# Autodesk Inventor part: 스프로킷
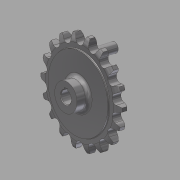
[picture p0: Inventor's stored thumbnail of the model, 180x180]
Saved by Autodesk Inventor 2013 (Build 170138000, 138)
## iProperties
Created: 2016-03
Part Number: 스프로킷
Material: 강철, 탄소
Document SubType Name: Modeling
Designer: mduedu
Density: 7.87 g/cm^3
Mass: 301.857 g
Surface Area: 120.622 cm^2
Volume: 38.3554 cm^3
Author: mduedu
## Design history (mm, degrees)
sketch "스케치1"
  geometry: L1 (0, 5)-(29.5, 5); L2 (29.5, 5)-(29.5, 4.1); L3 (30, 3.6)-(33.625, 3.6); L4 (40, 2)-(40, 0); L5 (40, 0)-(0, 0); L6 (0, 0)-(0, 5); L7 (0, -5)-(29.5, -5); L8 (29.5, -5)-(29.5, -4.1); L9 (30, -3.6)-(33.625, -3.6); L10 (40, -2)-(40, 0); L11 (0, 0)-(0, -5); A1 r 13.5 centre (33.625, -9.9) between (40, 2) and (33.625, 3.6); A2 r 13.5 centre (33.625, 9.9) between (33.625, -3.6) and (40, -2); A3 r 0.5 centre (30, 4.1) between (29.5, 4.1) and (30, 3.6); A4 r 0.5 centre (30, -4.1) between (30, -3.6) and (29.5, -4.1); 2 further points
  constraints: 22 end point, 8 point on circle, 6 symmetric about line, 5 tangent, 4 centre point, 4 parallel, 4 point on line, 1 equal radius, 1 horizontal, 1 perpendicular, 1 other
  dimensions: "d0" = 80 diameter of L4 L6; "d2" = 59 diameter of L2 L6; "d3" = 1.6 vertical distance of L4.start L3.end; "d4" = 3.6 distance from line of L4.end L3; "d5" = 5 distance between parallel lines of L5 L1; "d6" = 13.5 radius of A1; "d15" = 0.5 radius of A3
revolve "회전1" sketch "스케치1" stored, may be unused: angle "d7" = 90 deg
sketch "스케치2" dims "d8" = 65.2, "d11" = 80
  geometry: L1 (0, 0)-(0, 32.6); A1 r 36.57 centre (0, 0) between (-16.231, 32.771) and (0, 36.57); A2 r 3.97 centre (0, 36.57) between (-3.866, 35.665) and (0, 32.6); A3 r 12.7 centre (-16.231, 32.771) between (-3.866, 35.665) and (-5.534, 39.615); A4 r 12.7 centre (16.231, 32.771) between (5.534, 39.615) and (3.866, 35.665); A5 r 3.97 centre (0, 36.57) between (0, 32.6) and (3.866, 35.665); A6 r 40 centre (0, 0) between (5.534, 39.615) and (-5.534, 39.615); 2 further points
  constraints: 12 point on circle, 6 centre point, 4 coincident, 3 symmetric about line, 2 end point, 1 point on line, 1 tangent, 1 vertical, 1 vertical alignment, 7 other
  dimensions: "d10" = 73.14 diameter of A1; "d12" = 12.7 radius of A3
extrude "돌출1" cut sketch "스케치2" stored distance "d13" = 10; taper "d14" = 0 deg
sketch "스케치3"
  geometry: C1 r 11 at (0, 0); 1 further point
  constraints: 1 centre point, 1 coincident
  dimensions: "d19" = 22 diameter of C1
extrude "돌출2" join sketch "스케치3" distance "d20" = 10; taper "d21" = 0 deg
fillet "모깎기1" dims "d22" = 3
sketch "스케치4"
  geometry: L1 (-1.5, 0)-(1.5, 0); L2 (1.5, 0)-(1.5, 6.4); L3 (1.5, 6.4)-(-1.5, 6.4); L4 (-1.5, 6.4)-(-1.5, 0); C1 r 5 at (0, 0); 2 further points
  constraints: 8 end point, 2 coincident, 2 parallel, 1 centre point, 1 horizontal, 1 midpoint, 1 perpendicular
  dimensions: "d23" = 10 diameter of C1; "d25" = 3 distance of L2.end L3.end; "d26" = 6.4 distance of L1.end L2.end
extrude "돌출3" cut sketch "스케치4" stored distance "d27" = 8; taper "d28" = 0 deg
chamfer "모따기1" distance "d29" = 0.5; stored, may be unused: second distance "d30" = 2, angle "d31" = 45 deg
sketch "스케치5" dims "d33" = 48
  geometry: C1 r 4 at (0, 24); 2 further points
  constraints: 2 vertical alignment, 1 centre point, 1 coincident, 2 other
  dimensions: "d32" = 8 diameter of C1
extrude "돌출4" join sketch "스케치5" distance "d34" = 20; taper "d35" = 0 deg
fillet "모깎기2" dims "d36" = 1
hole "구멍1" diameter "d39" = 3.242; stored, may be unused: countersink angle "d43" = 90 deg, drill point angle "d45" = 118 deg; dims "d40" = 8, "d41" = 4, "d42" = 2, "d44" = 10, "d46" = 10, "d47" = 10
node "솔리드1"
pattern_circular "원형 패턴1" dims angle "d17" = 360 deg
